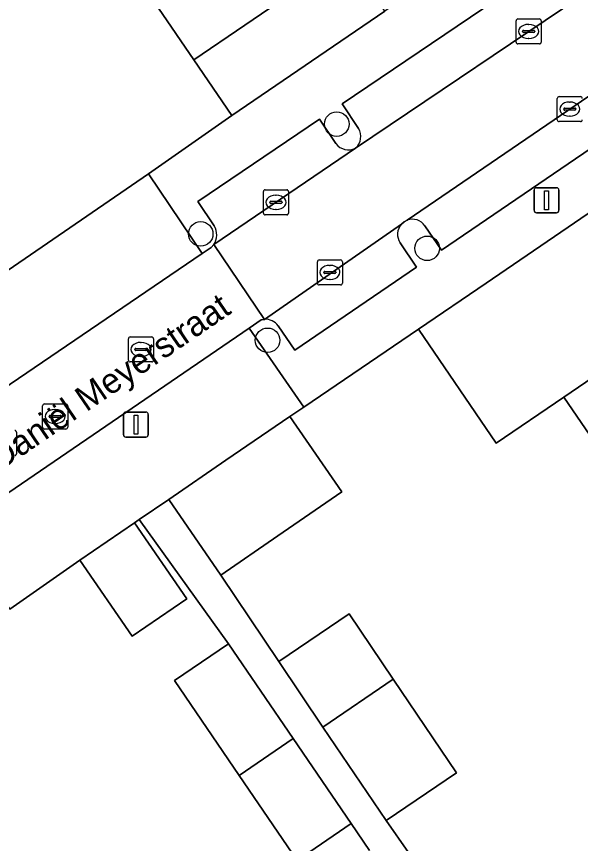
# Model space of a CAD drawing. Extents: x 157445 to 158888, y 383061 to 384688.
# Drawn here: x 158169.19 to 158191.67, y 383839.96 to 383872.93 of the extents above; entities that cross this region are included whole.
import ezdxf

# ---------------------------------------------------------------- set-up
doc = ezdxf.new("R2010")
doc.units = 0
for name, color, linetype in [('IMGEO_Boom', 7, 'Continuous'), ('IMGEO_Erf', 7, 'Continuous'), ('IMGEO_Kolk', 7, 'Continuous'), ('IMGEO_Lichtmast', 7, 'Continuous'), ('IMGEO_Muur', 7, 'Continuous'), ('IMGEO_Openbare_ruimte_label', 7, 'Continuous'), ('IMGEO_Pand', 7, 'Continuous'), ('IMGEO_Parkeervlak_open', 7, 'Continuous'), ('IMGEO_Rijbaan_lokaal_open', 7, 'Continuous'), ('IMGEO_Rioolput', 7, 'Continuous'), ('IMGEO_Voetpad_open', 7, 'Continuous')]:
    doc.layers.add(name, color=color, linetype=linetype)

msp = doc.modelspace()

# ---------------------------------------------------------------- linework, layer by layer
at = {"layer": 'IMGEO_Boom'}
for centre in [(158181.952, 383868.643), (158176.53, 383864.264), (158185.555, 383863.689), (158179.194, 383860.022)]:
    msp.add_circle(centre, 0.489, dxfattribs=at)
at = {"layer": 'IMGEO_Erf'}
for points in [[(158160.678, 383874.344), (158162.861, 383871.09), (158160.809, 383869.69), (158162.688, 383866.89), (158164.525, 383868.143), (158165.013, 383868.476), (158167.156, 383865.28), (158164.916, 383863.738), (158166.598, 383861.278), (158174.453, 383866.663), (158177.767, 383868.99), (158176.255, 383871.207), (158173.437, 383875.338)], [(158206.199, 383835.479), (158203.111, 383840.006), (158200.197, 383844.277), (158197.074, 383848.856), (158194.136, 383853.163), (158191.002, 383857.757), (158188.309, 383855.92), (158185.208, 383860.465), (158180.642, 383857.353), (158180.085, 383856.988), (158182.156, 383853.977), (158179.608, 383852.225), (158177.334, 383850.661), (158179.637, 383847.212), (158182.448, 383849.11), (158184.202, 383846.512), (158186.726, 383842.774), (158183.915, 383840.876), (158185.698, 383838.326)], [(158183.256, 383839.678), (158182.525, 383840.75), (158180.377, 383839.278), (158178.065, 383842.667), (158175.48, 383846.456), (158177.631, 383847.924), (158174.081, 383852.874), (158173.891, 383852.746), (158175.974, 383849.718), (158173.798, 383848.22), (158171.715, 383851.248), (158168.916, 383849.294)]]:
    msp.add_lwpolyline(points, dxfattribs=at)
at = {"layer": 'IMGEO_Kolk'}
for p, q in [((158189.1, 383871.911), (158189.1, 383872.763)), ((158189.175, 383872.837), (158190.027, 383872.837)), ((158190.101, 383872.763), (158190.101, 383871.911)), ((158189.588, 383872.617), (158189.613, 383872.617)), ((158189.359, 383872.331), (158189.359, 383872.343)), ((158189.797, 383872.294), (158189.399, 383872.294)), ((158189.402, 383872.38), (158189.8, 383872.38)), ((158189.843, 383872.343), (158189.843, 383872.331)), ((158190.027, 383871.837), (158189.175, 383871.837)), ((158189.611, 383872.057), (158189.586, 383872.057)), ((158190.738, 383868.815), (158190.738, 383869.667)), ((158190.813, 383869.741), (158191.665, 383869.741)), ((158191.226, 383869.521), (158191.251, 383869.521)), ((158190.997, 383869.235), (158190.997, 383869.247)), ((158191.435, 383869.198), (158191.037, 383869.198)), ((158191.04, 383869.284), (158191.438, 383869.284)), ((158191.481, 383869.247), (158191.481, 383869.235)), ((158191.249, 383868.961), (158191.224, 383868.961)), ((158191.665, 383868.741), (158190.813, 383868.741)), ((158179.029, 383865.097), (158179.029, 383865.949)), ((158179.104, 383866.023), (158179.956, 383866.023)), ((158180.03, 383865.949), (158180.03, 383865.097)), ((158179.288, 383865.517), (158179.288, 383865.529)), ((158179.726, 383865.48), (158179.328, 383865.48)), ((158179.331, 383865.566), (158179.729, 383865.566)), ((158179.517, 383865.803), (158179.542, 383865.803)), ((158179.772, 383865.529), (158179.772, 383865.517)), ((158179.54, 383865.243), (158179.515, 383865.243)), ((158179.956, 383865.023), (158179.104, 383865.023)), ((158181.254, 383863.228), (158182.106, 383863.228)), ((158181.179, 383862.302), (158181.179, 383863.154)), ((158181.667, 383863.008), (158181.692, 383863.008)), ((158182.18, 383863.154), (158182.18, 383862.302)), ((158181.438, 383862.722), (158181.438, 383862.734)), ((158181.876, 383862.685), (158181.478, 383862.685)), ((158181.481, 383862.771), (158181.879, 383862.771)), ((158181.922, 383862.734), (158181.922, 383862.722)), ((158182.106, 383862.228), (158181.254, 383862.228)), ((158181.69, 383862.448), (158181.665, 383862.448)), ((158173.648, 383859.231), (158173.648, 383860.083)), ((158173.723, 383860.157), (158174.575, 383860.157)), ((158174.136, 383859.937), (158174.161, 383859.937)), ((158174.649, 383860.083), (158174.649, 383859.231)), ((158173.907, 383859.651), (158173.907, 383859.663)), ((158174.345, 383859.614), (158173.947, 383859.614)), ((158173.95, 383859.7), (158174.348, 383859.7)), ((158174.391, 383859.663), (158174.391, 383859.651)), ((158174.159, 383859.377), (158174.134, 383859.377)), ((158174.575, 383859.157), (158173.723, 383859.157)), ((158169.189, 383856.352), (158169.189, 383855.5))]:
    msp.add_line(p, q, dxfattribs=at)
for points in [[(158189.1, 383871.911), (158189.1, 383872.763)], [(158189.175, 383872.837), (158190.027, 383872.837)], [(158190.101, 383872.763), (158190.101, 383871.911)], [(158190.027, 383871.837), (158189.175, 383871.837)], [(158190.738, 383868.815), (158190.738, 383869.667)], [(158190.813, 383869.741), (158191.665, 383869.741)], [(158191.665, 383868.741), (158190.813, 383868.741)], [(158179.029, 383865.097), (158179.029, 383865.949)], [(158179.104, 383866.023), (158179.956, 383866.023)], [(158180.03, 383865.949), (158180.03, 383865.097)], [(158179.956, 383865.023), (158179.104, 383865.023)], [(158181.254, 383863.228), (158182.106, 383863.228)], [(158181.179, 383862.302), (158181.179, 383863.154)], [(158182.18, 383863.154), (158182.18, 383862.302)], [(158182.106, 383862.228), (158181.254, 383862.228)], [(158173.648, 383859.231), (158173.648, 383860.083)], [(158173.723, 383860.157), (158174.575, 383860.157)], [(158174.649, 383860.083), (158174.649, 383859.231)], [(158174.575, 383859.157), (158173.723, 383859.157)], [(158169.189, 383856.352), (158169.189, 383855.5)]]:
    msp.add_lwpolyline(points, dxfattribs=at)
for centre, radius, start, end in [((158189.177, 383872.761), 0.0765, 91.552, 178.448), ((158189.177, 383872.761), 0.0765, 91.552, 178.448), ((158190.025, 383872.761), 0.0765, 1.552, 88.448), ((158190.025, 383872.761), 0.0765, 1.552, 88.448), ((158189.399, 383872.34), 0.0403, 85.8775, 175.7526), ((158189.396, 383872.33), 0.0366, 178.938, 274.7102), ((158189.8, 383872.337), 0.043, 264.8664, 352.4533), ((158189.804, 383872.342), 0.0386, 1.7309, 96.639), ((158189.177, 383871.913), 0.0765, 181.552, 268.448), ((158189.177, 383871.913), 0.0765, 181.552, 268.448), ((158190.025, 383871.913), 0.0765, 271.552, 358.448), ((158190.025, 383871.913), 0.0765, 271.552, 358.448), ((158190.815, 383869.665), 0.0765, 91.552, 178.448), ((158190.815, 383869.665), 0.0765, 91.552, 178.448), ((158191.663, 383869.665), 0.0765, 1.552, 88.448), ((158191.663, 383869.665), 0.0765, 1.552, 88.448), ((158191.037, 383869.244), 0.0403, 85.8775, 175.7526), ((158191.034, 383869.234), 0.0366, 178.938, 274.7102), ((158191.438, 383869.241), 0.043, 264.8664, 352.4533), ((158191.442, 383869.246), 0.0386, 1.7309, 96.639), ((158190.815, 383868.817), 0.0765, 181.552, 268.448), ((158190.815, 383868.817), 0.0765, 181.552, 268.448), ((158191.663, 383868.817), 0.0765, 271.552, 358.448), ((158191.663, 383868.817), 0.0765, 271.552, 358.448), ((158179.106, 383865.947), 0.0765, 91.552, 178.448), ((158179.106, 383865.947), 0.0765, 91.552, 178.448), ((158179.954, 383865.947), 0.0765, 1.552, 88.448), ((158179.954, 383865.947), 0.0765, 1.552, 88.448), ((158179.328, 383865.526), 0.0403, 85.8775, 175.7526), ((158179.325, 383865.516), 0.0366, 178.938, 274.7102), ((158179.729, 383865.523), 0.043, 264.8664, 352.4533), ((158179.733, 383865.528), 0.0386, 1.7309, 96.639), ((158179.106, 383865.099), 0.0765, 181.552, 268.448), ((158179.106, 383865.099), 0.0765, 181.552, 268.448), ((158179.954, 383865.099), 0.0765, 271.552, 358.448), ((158179.954, 383865.099), 0.0765, 271.552, 358.448), ((158181.256, 383863.152), 0.0765, 91.552, 178.448), ((158181.256, 383863.152), 0.0765, 91.552, 178.448), ((158182.104, 383863.152), 0.0765, 1.552, 88.448), ((158182.104, 383863.152), 0.0765, 1.552, 88.448), ((158181.478, 383862.731), 0.0403, 85.8775, 175.7526), ((158181.475, 383862.721), 0.0366, 178.938, 274.7102), ((158181.879, 383862.728), 0.043, 264.8664, 352.4533), ((158181.883, 383862.733), 0.0386, 1.7309, 96.639), ((158181.256, 383862.304), 0.0765, 181.552, 268.448), ((158181.256, 383862.304), 0.0765, 181.552, 268.448), ((158182.104, 383862.304), 0.0765, 271.552, 358.448), ((158182.104, 383862.304), 0.0765, 271.552, 358.448), ((158173.725, 383860.081), 0.0765, 91.552, 178.448), ((158173.725, 383860.081), 0.0765, 91.552, 178.448), ((158174.573, 383860.081), 0.0765, 1.552, 88.448), ((158174.573, 383860.081), 0.0765, 1.552, 88.448), ((158173.947, 383859.66), 0.0403, 85.8775, 175.7526), ((158173.944, 383859.65), 0.0366, 178.938, 274.7102), ((158174.348, 383859.657), 0.043, 264.8664, 352.4533), ((158174.352, 383859.662), 0.0386, 1.7309, 96.639), ((158173.725, 383859.233), 0.0765, 181.552, 268.448), ((158173.725, 383859.233), 0.0765, 181.552, 268.448), ((158174.573, 383859.233), 0.0765, 271.552, 358.448), ((158174.573, 383859.233), 0.0765, 271.552, 358.448), ((158169.113, 383856.35), 0.0765, 1.552, 88.448), ((158169.113, 383856.35), 0.0765, 1.552, 88.448), ((158169.113, 383855.502), 0.0765, 271.552, 358.448), ((158169.113, 383855.502), 0.0765, 271.552, 358.448)]:
    msp.add_arc(centre, radius, start, end, dxfattribs=at)
for centre, major_axis, ratio, start_param, end_param in [((158189.587, 383872.337), (-0.387, 0.002), 0.722429, 4.712389, 7.853982), ((158189.612, 383872.337), (-0.39, 0.002), 0.717154, 1.570796, 4.712389), ((158191.225, 383869.241), (-0.387, 0.002), 0.722429, 4.712389, 7.853982), ((158191.25, 383869.241), (-0.39, 0.002), 0.717154, 1.570796, 4.712389), ((158179.516, 383865.523), (-0.387, 0.002), 0.722429, 4.712389, 7.853982), ((158179.541, 383865.523), (-0.39, 0.002), 0.717154, 1.570796, 4.712389), ((158181.666, 383862.728), (-0.387, 0.002), 0.722429, 4.712389, 7.853982), ((158181.691, 383862.728), (-0.39, 0.002), 0.717154, 1.570796, 4.712389), ((158174.135, 383859.657), (-0.387, 0.002), 0.722429, 4.712389, 7.853982), ((158174.16, 383859.657), (-0.39, 0.002), 0.717154, 1.570796, 4.712389)]:
    msp.add_ellipse(centre, major_axis=major_axis, ratio=ratio, start_param=start_param, end_param=end_param, dxfattribs=at)
at = {"layer": 'IMGEO_Lichtmast'}
for p, q in [((158189.818, 383865.205), (158189.818, 383866.005)), ((158189.818, 383866.005), (158189.818, 383865.205)), ((158189.918, 383866.105), (158190.708, 383866.105)), ((158190.708, 383866.105), (158189.918, 383866.105)), ((158190.808, 383866.005), (158190.808, 383865.205)), ((158190.808, 383865.205), (158190.808, 383866.005)), ((158190.708, 383865.105), (158189.918, 383865.105)), ((158189.918, 383865.105), (158190.708, 383865.105)), ((158173.451, 383856.258), (158173.451, 383857.058)), ((158173.451, 383857.058), (158173.451, 383856.258)), ((158173.551, 383857.158), (158174.341, 383857.158)), ((158174.341, 383857.158), (158173.551, 383857.158)), ((158174.441, 383857.058), (158174.441, 383856.258)), ((158174.441, 383856.258), (158174.441, 383857.058)), ((158174.341, 383856.158), (158173.551, 383856.158)), ((158173.551, 383856.158), (158174.341, 383856.158))]:
    msp.add_line(p, q, dxfattribs=at)
for points in [[(158190.238, 383865.98), (158190.388, 383865.98), (158190.388, 383865.23), (158190.238, 383865.23), (158190.238, 383865.98)], [(158173.871, 383857.033), (158174.021, 383857.033), (158174.021, 383856.283), (158173.871, 383856.283), (158173.871, 383857.033)]]:
    msp.add_lwpolyline(points, dxfattribs=at)
for centre, start, end in [((158189.918, 383866.005), 90, 180), ((158189.918, 383866.005), 90, 180), ((158190.708, 383866.005), 0, 90), ((158190.708, 383866.005), 360, 90), ((158189.918, 383865.205), 180, 270), ((158189.918, 383865.205), 180, 270), ((158190.708, 383865.205), 270, 0), ((158190.708, 383865.205), 270, 0), ((158173.551, 383857.058), 90, 180), ((158173.551, 383857.058), 90, 180), ((158174.341, 383857.058), 0, 90), ((158174.341, 383857.058), 360, 90), ((158173.551, 383856.258), 180, 270), ((158173.551, 383856.258), 180, 270), ((158174.341, 383856.258), 270, 0), ((158174.341, 383856.258), 270, 0)]:
    msp.add_arc(centre, 0.1, start, end, dxfattribs=at)
at = {"layer": 'IMGEO_Muur'}
msp.add_lwpolyline([(158185.422, 383860.612), (158187.901, 383862.302)], dxfattribs=at)
at = {"layer": 'IMGEO_Pand'}
for points in [[(158183.336, 383876.038), (158180.061, 383880.838), (158172.98, 383876.007), (158173.437, 383875.338), (158176.255, 383871.207), (158182.351, 383875.366), (158182.612, 383875.544)], [(158183.864, 383873.149), (158182.351, 383875.366), (158176.255, 383871.207), (158177.767, 383868.99)], [(158198.052, 383862.567), (158194.952, 383867.112), (158187.901, 383862.302), (158185.208, 383860.465), (158188.309, 383855.92), (158191.002, 383857.757)], [(158198.052, 383862.567), (158191.002, 383857.757), (158194.136, 383853.163), (158201.186, 383857.973)], [(158180.085, 383856.988), (158177.537, 383855.236), (158175.263, 383853.672), (158177.334, 383850.661), (158179.608, 383852.225), (158182.156, 383853.977)], [(158173.891, 383852.746), (158171.715, 383851.248), (158173.798, 383848.22), (158175.974, 383849.718)], [(158184.202, 383846.512), (158182.448, 383849.11), (158179.637, 383847.212), (158181.401, 383844.6)], [(158180.213, 383844.139), (158177.631, 383847.924), (158175.48, 383846.456), (158178.065, 383842.667)], [(158184.202, 383846.512), (158181.401, 383844.6), (158183.915, 383840.876), (158186.726, 383842.774)], [(158180.213, 383844.139), (158178.065, 383842.667), (158180.377, 383839.278), (158182.525, 383840.75)]]:
    msp.add_lwpolyline(points, close=True, dxfattribs=at)
at = {"layer": 'IMGEO_Parkeervlak_open'}
for points in [[(158191.502, 383874.348), (158190.846, 383875.319), (158182.164, 383869.444), (158182.821, 383868.473)], [(158182.701, 383867.68), (158192.336, 383874.187)], [(158194.216, 383871.269), (158184.757, 383864.806)], [(158185.467, 383864.584), (158186.127, 383863.616), (158194.761, 383869.498), (158194.101, 383870.467)], [(158181.92, 383867.864), (158181.264, 383868.835), (158176.413, 383865.553), (158177.07, 383864.582)], [(158177.051, 383863.841), (158182.701, 383867.68)], [(158184.528, 383864.65), (158179.069, 383860.857)], [(158179.615, 383860.598), (158180.275, 383859.629), (158185.137, 383862.941), (158184.477, 383863.91)]]:
    msp.add_lwpolyline(points, dxfattribs=at)
for centre, radius, start, end in [((158182.283, 383868.149), 0.628, 311.7361, 31.054), ((158182.421, 383868.242), 0.628, 217.02, 296.4662), ((158184.973, 383864.249), 0.597, 34.1099, 111.1637), ((158176.488, 383864.226), 0.682, 325.6037, 31.4587), ((158184.971, 383864.248), 0.598, 137.7508, 214.3642), ((158179.119, 383860.258), 0.601, 34.4649, 94.7796)]:
    msp.add_arc(centre, radius, start, end, dxfattribs=at)
at = {"layer": 'IMGEO_Rijbaan_lokaal_open'}
for points in [[(158179.069, 383860.857), (158184.528, 383864.65), (158184.634, 383864.742), (158184.757, 383864.806), (158194.216, 383871.269), (158195.62, 383872.228), (158193.691, 383875.104), (158192.336, 383874.187), (158182.701, 383867.68), (158177.051, 383863.841)], [(158166.769, 383852.518), (158178.463, 383860.506), (158178.94, 383860.832), (158179.069, 383860.857), (158177.051, 383863.841), (158176.951, 383863.726), (158176.586, 383863.476), (158164.806, 383855.465), (158164.383, 383855.174), (158164.231, 383855.099), (158166.287, 383852.155), (158166.388, 383852.257)]]:
    msp.add_lwpolyline(points, close=True, dxfattribs=at)
at = {"layer": 'IMGEO_Rioolput'}
for p, q in [((158170.228, 383856.558), (158170.228, 383857.41)), ((158170.303, 383857.484), (158171.155, 383857.484)), ((158170.716, 383857.264), (158170.741, 383857.264)), ((158171.229, 383857.41), (158171.229, 383856.558)), ((158170.487, 383856.978), (158170.487, 383856.99)), ((158170.925, 383856.941), (158170.527, 383856.941)), ((158170.53, 383857.027), (158170.928, 383857.027)), ((158170.971, 383856.99), (158170.971, 383856.978)), ((158170.739, 383856.704), (158170.714, 383856.704)), ((158171.155, 383856.484), (158170.303, 383856.484))]:
    msp.add_line(p, q, dxfattribs=at)
for points in [[(158170.228, 383856.558), (158170.228, 383857.41)], [(158170.303, 383857.484), (158171.155, 383857.484)], [(158171.229, 383857.41), (158171.229, 383856.558)], [(158171.155, 383856.484), (158170.303, 383856.484)]]:
    msp.add_lwpolyline(points, dxfattribs=at)
for centre, radius, start, end in [((158170.305, 383857.408), 0.0765, 91.552, 178.448), ((158170.305, 383857.408), 0.0765, 91.552, 178.448), ((158171.153, 383857.408), 0.0765, 1.552, 88.448), ((158171.153, 383857.408), 0.0765, 1.552, 88.448), ((158170.527, 383856.987), 0.0403, 85.8775, 175.7526), ((158170.524, 383856.977), 0.0366, 178.938, 274.7102), ((158170.928, 383856.984), 0.043, 264.8664, 352.4533), ((158170.932, 383856.989), 0.0386, 1.7309, 96.639), ((158170.305, 383856.56), 0.0765, 181.552, 268.448), ((158170.305, 383856.56), 0.0765, 181.552, 268.448), ((158171.153, 383856.56), 0.0765, 271.552, 358.448), ((158171.153, 383856.56), 0.0765, 271.552, 358.448)]:
    msp.add_arc(centre, radius, start, end, dxfattribs=at)
for centre, major_axis, ratio, start_param, end_param in [((158170.715, 383856.984), (-0.387, 0.002), 0.722429, 4.712389, 7.853982), ((158170.74, 383856.984), (-0.39, 0.002), 0.717154, 1.570796, 4.712389)]:
    msp.add_ellipse(centre, major_axis=major_axis, ratio=ratio, start_param=start_param, end_param=end_param, dxfattribs=at)
at = {"layer": 'IMGEO_Voetpad_open'}
for points in [[(158190.846, 383875.319), (158189.73, 383877.146), (158183.864, 383873.149), (158177.767, 383868.99), (158174.453, 383866.663), (158176.586, 383863.476), (158176.951, 383863.726), (158177.051, 383863.841)], [(158182.821, 383868.473), (158182.164, 383869.444), (158190.846, 383875.319)], [(158194.952, 383867.112), (158196.185, 383867.993), (158194.761, 383869.498), (158186.127, 383863.616), (158185.467, 383864.584)], [(158177.07, 383864.582), (158176.413, 383865.553), (158181.264, 383868.835), (158181.92, 383867.864)], [(158179.069, 383860.857), (158178.94, 383860.832), (158178.463, 383860.506), (158180.642, 383857.353), (158185.208, 383860.465), (158187.901, 383862.302), (158194.952, 383867.112)], [(158184.757, 383864.806), (158184.634, 383864.742), (158184.528, 383864.65)], [(158184.477, 383863.91), (158185.137, 383862.941), (158180.275, 383859.629), (158179.615, 383860.598)], [(158185.698, 383838.326), (158183.915, 383840.876), (158181.401, 383844.6), (158179.637, 383847.212), (158177.334, 383850.661), (158175.263, 383853.672), (158174.081, 383852.874), (158177.631, 383847.924), (158180.213, 383844.139), (158182.525, 383840.75), (158183.256, 383839.678)]]:
    msp.add_lwpolyline(points, dxfattribs=at)
for points in [[(158176.586, 383863.476), (158174.453, 383866.663), (158166.598, 383861.278), (158166.758, 383861.044), (158165.485, 383860.173), (158162.867, 383858.377), (158164.806, 383855.465)], [(158177.537, 383855.236), (158180.085, 383856.988), (158180.642, 383857.353), (158178.463, 383860.506), (158166.769, 383852.518), (158168.916, 383849.294), (158171.715, 383851.248), (158173.891, 383852.746), (158174.081, 383852.874), (158175.263, 383853.672)]]:
    msp.add_lwpolyline(points, close=True, dxfattribs=at)
for centre, radius, start, end in [((158182.283, 383868.149), 0.628, 311.7361, 31.054), ((158182.421, 383868.242), 0.628, 217.02, 296.4662), ((158184.973, 383864.249), 0.597, 34.1099, 111.1637), ((158176.488, 383864.226), 0.682, 325.6037, 31.4587), ((158184.971, 383864.248), 0.598, 137.7508, 214.3642), ((158179.119, 383860.258), 0.601, 34.4649, 94.7796)]:
    msp.add_arc(centre, radius, start, end, dxfattribs=at)

# ---------------------------------------------------------------- texts
at = {"layer": 'IMGEO_Openbare_ruimte_label'}
msp.add_text('Jonas Daniël Meyerstraat', height=1, rotation=34.3256, dxfattribs=at).set_placement((158165.279, 383852.578))

doc.saveas('drawing.dxf')
